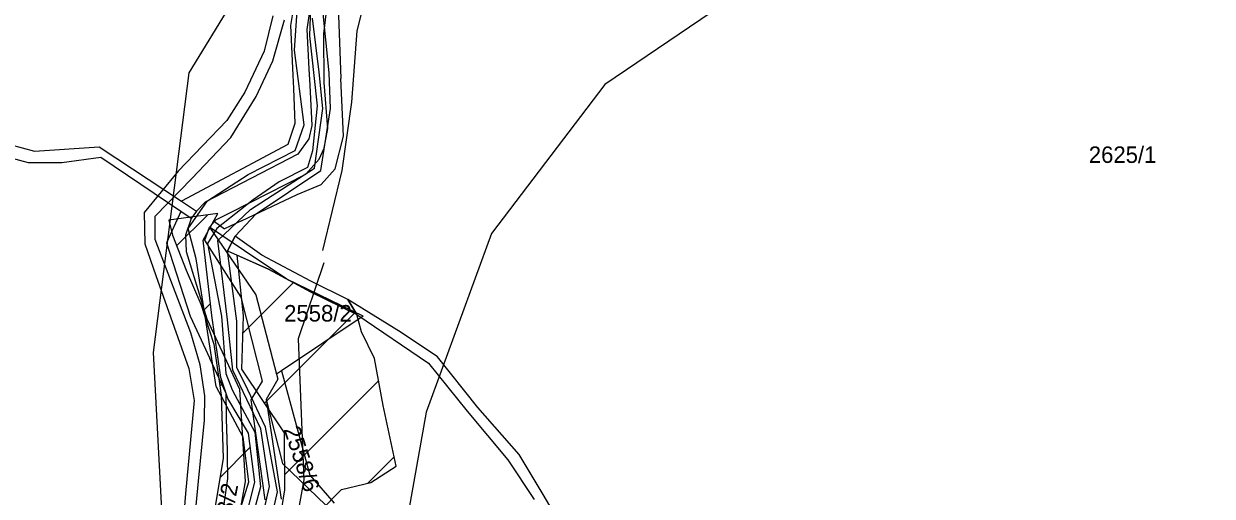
# Model space of a CAD drawing. Extents: x -564810 to -550519, y -1045831 to -1034011.
# Drawn here: x -551637.3 to -551270.6, y -1037442.3 to -1037296.5 of the extents above; entities that cross this region are included whole.
import ezdxf

# ---------------------------------------------------------------- set-up
doc = ezdxf.new("R2010")
doc.units = 0
for name, color, linetype in [('KN stav', 7, 'Continuous'), ('Lesní porost', 7, 'Continuous'), ('Parcelní čísla', 7, 'Continuous'), ('Polní cesty stavající', 7, 'Continuous'), ('STG', 7, 'Continuous'), ('vodní toky', 7, 'Continuous'), ('Vrstva 18', 7, 'Continuous'), ('Vrstva 33', 7, 'Continuous')]:
    doc.layers.add(name, color=color, linetype=linetype)

msp = doc.modelspace()

# ---------------------------------------------------------------- linework, layer by layer
at = {"layer": 'KN stav'}
for p, q in [((-551549.14, -1037261), (-551555, -1037297.05)), ((-551547.78, -1037282.89), (-551549.99, -1037298.21)), ((-551544.79, -1037299.56), (-551542.87, -1037283.57)), ((-551540.36, -1037291.18), (-551539.45, -1037313.36)), ((-551555, -1037297.05), (-551554.32, -1037312.32)), ((-551549.99, -1037298.21), (-551549.36, -1037310.41)), ((-551544.6, -1037314.59), (-551544.79, -1037299.56)), ((-551554.32, -1037312.32), (-551554.13, -1037316.42)), ((-551549.36, -1037310.41), (-551549.1, -1037315.39)), ((-551554.13, -1037316.42), (-551553.65, -1037327.22)), ((-551549.1, -1037315.39), (-551548.45, -1037327.89)), ((-551543.54, -1037328.85), (-551544.6, -1037314.59)), ((-551538.72, -1037331.17), (-551539.45, -1037313.36)), ((-551553.65, -1037327.22), (-551555.87, -1037333.7)), ((-551654.6, -1037330.27), (-551634.05, -1037335.84)), ((-551548.45, -1037327.89), (-551549.41, -1037331.94)), ((-551544.6, -1037334.83), (-551543.54, -1037328.85)), ((-551541.23, -1037341.28), (-551538.72, -1037331.17)), ((-551635.85, -1037339.35), (-551655.43, -1037334.29)), ((-551634.05, -1037335.84), (-551614.07, -1037334.46)), ((-551614.07, -1037334.46), (-551588.68, -1037351.23)), ((-551555.87, -1037333.7), (-551588.68, -1037351.23)), ((-551549.41, -1037331.94), (-551552.72, -1037336.73)), ((-551546.14, -1037338.3), (-551544.6, -1037334.83)), ((-551613.54, -1037337.73), (-551625.54, -1037339.35)), ((-551588.88, -1037354.41), (-551613.54, -1037337.73)), ((-551552.72, -1037336.73), (-551581.34, -1037351.54)), ((-551550.26, -1037342.85), (-551546.14, -1037338.3)), ((-551625.54, -1037339.35), (-551635.85, -1037339.35)), ((-551545.56, -1037346.1), (-551541.23, -1037341.28)), ((-551573.54, -1037354.7), (-551550.26, -1037342.85)), ((-551570.18, -1037357.29), (-551552.98, -1037349.14)), ((-551552.98, -1037349.14), (-551545.56, -1037346.1)), ((-551588.68, -1037351.23), (-551583.99, -1037354.33)), ((-551581.34, -1037351.54), (-551583.99, -1037354.33)), ((-551588.88, -1037354.41), (-551593.33, -1037364.13)), ((-551585.71, -1037356.56), (-551588.88, -1037354.41)), ((-551585.71, -1037356.56), (-551587.46, -1037361.73)), ((-551583.99, -1037354.33), (-551585.71, -1037356.56)), ((-551578.51, -1037357.51), (-551578.03, -1037356.98)), ((-551578.03, -1037356.98), (-551573.54, -1037354.7)), ((-551581.5, -1037363.31), (-551580.06, -1037359.22)), ((-551580.06, -1037359.22), (-551578.51, -1037357.51)), ((-551580.06, -1037359.22), (-551565.71, -1037380.15)), ((-551569.26, -1037366.52), (-551580.06, -1037359.22)), ((-551578.51, -1037357.51), (-551575.41, -1037359.77)), ((-551570.18, -1037357.29), (-551575.41, -1037359.77)), ((-551593.33, -1037364.13), (-551586.01, -1037386.71)), ((-551587.46, -1037361.73), (-551587.26, -1037366.8)), ((-551570.22, -1037380.83), (-551581.5, -1037363.31)), ((-551587.26, -1037366.8), (-551580.8, -1037387.55)), ((-551556.19, -1037375.35), (-551569.26, -1037366.52)), ((-551532.57, -1037386.75), (-551556.19, -1037375.35)), ((-551563.67, -1037406.75), (-551570.22, -1037380.83)), ((-551565.71, -1037380.15), (-551559.34, -1037404.6)), ((-551586.01, -1037386.71), (-551579.91, -1037399.79)), ((-551580.8, -1037387.55), (-551570.74, -1037409.2)), ((-551532.57, -1037386.75), (-551557.8, -1037403.58)), ((-551574.89, -1037410.55), (-551579.91, -1037399.79)), ((-551557.8, -1037403.58), (-551559.34, -1037404.6)), ((-551559.34, -1037404.6), (-551558.94, -1037406.12)), ((-551557.8, -1037403.58), (-551549.04, -1037435.77)), ((-551567.21, -1037412.59), (-551563.67, -1037406.75)), ((-551558.94, -1037406.12), (-551562.54, -1037412.48)), ((-551574.71, -1037423.11), (-551574.89, -1037410.55)), ((-551570.74, -1037409.2), (-551569.04, -1037437.75)), ((-551562.83, -1037443.42), (-551567.21, -1037412.59)), ((-551562.54, -1037412.48), (-551557.93, -1037443.23)), ((-551562.54, -1037412.48), (-551557.46, -1037432.16)), ((-551574.71, -1037423.11), (-551574.51, -1037436.84)), ((-551557.46, -1037432.16), (-551538.81, -1037450.22)), ((-551574.51, -1037436.84), (-551581.67, -1037488.42)), ((-551549.04, -1037435.77), (-551541.51, -1037444.4)), ((-551569.04, -1037437.75), (-551573.47, -1037462.66))]:
    msp.add_line(p, q, dxfattribs=at)
at = {"layer": 'Lesní porost'}
for p, q in [((-551577.41, -1037355.08), (-551592.53, -1037357.12)), ((-551590.15, -1037365.03), (-551580.64, -1037355.52)), ((-551581.97, -1037363.24), (-551577.41, -1037355.08)), ((-551592.53, -1037357.12), (-551591.42, -1037361.75)), ((-551591.42, -1037361.75), (-551587.24, -1037372.53)), ((-551579.28, -1037386.47), (-551581.97, -1037363.24)), ((-551561.81, -1037372.19), (-551571.55, -1037367.87)), ((-551571.55, -1037367.87), (-551569.66, -1037386.57)), ((-551587.24, -1037372.53), (-551582.74, -1037382.99)), ((-551548.81, -1037379.24), (-551561.81, -1037372.19)), ((-551569.81, -1037392.05), (-551554.12, -1037376.36)), ((-551534.51, -1037386.16), (-551548.81, -1037379.24)), ((-551582.74, -1037382.99), (-551578.71, -1037395.36)), ((-551582.03, -1037385.18), (-551579.7, -1037382.86)), ((-551563.08, -1037413.61), (-551535.27, -1037385.79)), ((-551533.08, -1037391.53), (-551534.51, -1037386.16)), ((-551576.53, -1037405.69), (-551579.28, -1037386.47)), ((-551529.12, -1037399.79), (-551533.08, -1037391.53)), ((-551578.71, -1037395.36), (-551576.43, -1037411.12)), ((-551526.46, -1037414.29), (-551529.12, -1037399.79)), ((-551576.84, -1037408.28), (-551575.96, -1037407.4)), ((-551574.4, -1037412.1), (-551576.53, -1037405.69)), ((-551556.89, -1037435.69), (-551527.86, -1037406.67)), ((-551576.43, -1037411.12), (-551575.77, -1037430.58)), ((-551568, -1037422.82), (-551574.4, -1037412.1)), ((-551522.46, -1037433), (-551526.46, -1037414.29)), ((-551566.04, -1037437.9), (-551568, -1037422.82)), ((-551557.01, -1037422.74), (-551556.84, -1037440.36)), ((-551576.77, -1037436.49), (-551567.44, -1037427.16)), ((-551531.13, -1037438.23), (-551523.07, -1037430.16)), ((-551575.77, -1037430.58), (-551578.38, -1037446.09)), ((-551530.28, -1037438.02), (-551522.46, -1037433)), ((-551570.84, -1037456.9), (-551566.04, -1037437.9)), ((-551556.84, -1037440.36), (-551559, -1037452.99)), ((-551546.07, -1037447.06), (-551539.25, -1037440.2)), ((-551539.25, -1037440.2), (-551530.28, -1037438.02))]:
    msp.add_line(p, q, dxfattribs=at)
msp.add_lwpolyline([(-551569.66, -1037386.57), (-551570.11, -1037403.05), (-551557.01, -1037422.74)], dxfattribs=at)
at = {"layer": 'Polní cesty stavající'}
for p, q in [((-551560.51, -1037293.99), (-551563.12, -1037304.98)), ((-551560.5, -1037307.88), (-551556.86, -1037295.26)), ((-551563.12, -1037304.98), (-551569.1, -1037317.59)), ((-551565.59, -1037318.95), (-551560.5, -1037307.88)), ((-551569.1, -1037317.59), (-551574.68, -1037326.35)), ((-551573.46, -1037331.57), (-551565.59, -1037318.95)), ((-551574.68, -1037326.35), (-551589.67, -1037341.96)), ((-551585.5, -1037344.23), (-551573.46, -1037331.57)), ((-551589.67, -1037341.96), (-551600.21, -1037354.68)), ((-551596.83, -1037355.81), (-551585.5, -1037344.23)), ((-551600.21, -1037354.68), (-551600.01, -1037364.38)), ((-551596.74, -1037363.01), (-551596.83, -1037355.81)), ((-551600.01, -1037364.38), (-551596.55, -1037374.13)), ((-551585.8, -1037391.91), (-551596.74, -1037363.01)), ((-551572.05, -1037362.01), (-551574.5, -1037366.56)), ((-551563.89, -1037367.88), (-551572.05, -1037362.01)), ((-551574.5, -1037366.56), (-551561.82, -1037372.18)), ((-551548.75, -1037375.94), (-551563.89, -1037367.88)), ((-551596.55, -1037374.13), (-551586.41, -1037402.87)), ((-551561.82, -1037372.18), (-551548.82, -1037379.23)), ((-551537.37, -1037381.59), (-551548.75, -1037375.94)), ((-551548.82, -1037379.23), (-551534.52, -1037386.16)), ((-551520.84, -1037391.75), (-551537.37, -1037381.59)), ((-551537.37, -1037381.59), (-551534.52, -1037386.16)), ((-551534.52, -1037386.16), (-551537.37, -1037381.59)), ((-551534.52, -1037386.16), (-551512.41, -1037401.18)), ((-551582.88, -1037401.79), (-551585.8, -1037391.91)), ((-551509.69, -1037399.3), (-551520.84, -1037391.75)), ((-551497.25, -1037414.92), (-551509.69, -1037399.3)), ((-551586.41, -1037402.87), (-551584.78, -1037412.74)), ((-551581.42, -1037411.32), (-551582.88, -1037401.79)), ((-551512.41, -1037401.18), (-551500.5, -1037416)), ((-551581.53, -1037418.85), (-551581.42, -1037411.32)), ((-551584.78, -1037412.74), (-551587.46, -1037441.42)), ((-551484.45, -1037429.46), (-551497.25, -1037414.92)), ((-551583.45, -1037437.67), (-551581.53, -1037418.85)), ((-551500.5, -1037416), (-551487.94, -1037431.02)), ((-551477.07, -1037441.77), (-551484.45, -1037429.46)), ((-551487.94, -1037431.02), (-551479.85, -1037443.35)), ((-551584.87, -1037453.46), (-551583.45, -1037437.67)), ((-551587.46, -1037441.42), (-551588.3, -1037452.11)), ((-551466.24, -1037460.09), (-551477.07, -1037441.77))]:
    msp.add_line(p, q, dxfattribs=at)
at = {"layer": 'STG'}
for points in [[(-552085.98, -1037726.88), (-551997.79, -1037717.69), (-551885.73, -1037708.5), (-551777.34, -1037693.8), (-551650.58, -1037618.46), (-551597.31, -1037544.96), (-551593.63, -1037467.78), (-551597.31, -1037397.95), (-551586.28, -1037311.58), (-551545.87, -1037245.43), (-551516.47, -1037186.63), (-551459.52, -1037149.88), (-551378.69, -1037116.8), (-551273.98, -1037100.26), (-551202.33, -1037076.37), (-551108.64, -1037028.6), (-550987.39, -1036980.82), (-550890.39, -1036925.69), (-550831.6, -1036883.43), (-550758.12, -1036817.27), (-550710.36, -1036749.28), (-550693.82, -1036703.34), (-550693.82, -1036639.03), (-550758.12, -1036504.88)], [(-550827.93, -1037355.69), (-550859.16, -1037254.62), (-550894.07, -1037238.08), (-550932.64, -1037234.41), (-550974.9, -1037230.73), (-551004.29, -1037236.24), (-551042.87, -1037236.24), (-551074.1, -1037228.89), (-551120.03, -1037230.73), (-551145.75, -1037227.06), (-551221.07, -1037239.92), (-551287.2, -1037252.78), (-551358.85, -1037265.64), (-551412.13, -1037284.02), (-551458.06, -1037315.26), (-551492.96, -1037361.2), (-551513.17, -1037416.33), (-551527.86, -1037499.02)]]:
    msp.add_lwpolyline(points, dxfattribs=at)
at = {"layer": 'vodní toky'}
for p, q in [((-551548.65, -1037285.74), (-551549.21, -1037300.16)), ((-551543.06, -1037311.66), (-551545.12, -1037291.25)), ((-551549.21, -1037300.16), (-551547.8, -1037312.49)), ((-551547.8, -1037312.49), (-551546.77, -1037321.78)), ((-551542.68, -1037322.59), (-551543.06, -1037311.66)), ((-551546.77, -1037321.78), (-551548.19, -1037335.66)), ((-551545.66, -1037341.77), (-551542.68, -1037322.59)), ((-551565.58, -1037355.16), (-551545.66, -1037341.77)), ((-551558.52, -1037345.21), (-551566.5, -1037350.86)), ((-551566.5, -1037350.86), (-551577.78, -1037359.66)), ((-551572.05, -1037362.01), (-551565.58, -1037355.16)), ((-551577.78, -1037359.66), (-551580.68, -1037364.33)), ((-551580.68, -1037364.33), (-551576.29, -1037386.75)), ((-551574.5, -1037366.56), (-551572.05, -1037362.01)), ((-551571.58, -1037388.31), (-551574.5, -1037366.56)), ((-551576.29, -1037386.75), (-551574.94, -1037404.46)), ((-551571.63, -1037402.61), (-551571.58, -1037388.31)), ((-551574.94, -1037404.46), (-551572.99, -1037409.42)), ((-551568.15, -1037409.44), (-551571.63, -1037402.61)), ((-551572.99, -1037409.42), (-551565.99, -1037422.55)), ((-551562.77, -1037421.02), (-551568.15, -1037409.44)), ((-551565.99, -1037422.55), (-551564.33, -1037439.35)), ((-551559.02, -1037440.96), (-551562.77, -1037421.02)), ((-551564.33, -1037439.35), (-551568.83, -1037456.3)), ((-551562.61, -1037456.47), (-551559.02, -1037440.96))]:
    msp.add_line(p, q, dxfattribs=at)
msp.add_lwpolyline([(-551548.19, -1037335.66), (-551549.76, -1037340.8), (-551558.52, -1037345.21)], dxfattribs=at)
at = {"layer": 'Vrstva 18'}
for points in [[(-551219.35, -1037171.83), (-551273.07, -1037176.1), (-551316.99, -1037173.96), (-551342.14, -1037182.07), (-551357.92, -1037197.84), (-551387.33, -1037223), (-551432.53, -1037233.23), (-551453.63, -1037234.19), (-551488.38, -1037251.46), (-551528.78, -1037275.97), (-551534.54, -1037298.67), (-551536.24, -1037320.63), (-551539.23, -1037341.74), (-551545.19, -1037366.47)], [(-551571.94, -1037450.67), (-551567.89, -1037437.88), (-551569.59, -1037424.02), (-551577.91, -1037408.46), (-551584.09, -1037369.02), (-551586.65, -1037359.64), (-551580.68, -1037351.12), (-551568.1, -1037343.02), (-551553.6, -1037335.55), (-551550.83, -1037327.67), (-551553.82, -1037304.64), (-551552.11, -1037280.34)], [(-551544.76, -1037370.3), (-551552.65, -1037393.75), (-551550.94, -1037437.24), (-551554.78, -1037458.77), (-551534.74, -1037459.2), (-551525.57, -1037497.78), (-551513.85, -1037519.32), (-551505.75, -1037542.98), (-551507.66, -1037555.13), (-551531.75, -1037621), (-551553.07, -1037607.79), (-551573.11, -1037603.52), (-551613.4, -1037630.17), (-551651.35, -1037683.89), (-551693.56, -1037722.69)]]:
    msp.add_lwpolyline(points, dxfattribs=at)
at = {"layer": 'Vrstva 33'}
msp.add_lwpolyline([(-551566.42, -1037460.75), (-551561.55, -1037439.24), (-551564.16, -1037421.51), (-551572.79, -1037403.43), (-551574.45, -1037387.8), (-551577.49, -1037363.37), (-551567.35, -1037353.8), (-551547.64, -1037341.05), (-551545.04, -1037322.6), (-551546.2, -1037311.43), (-551548.23, -1037294.76)], dxfattribs=at)

# ---------------------------------------------------------------- texts
at = {"layer": 'Parcelní čísla'}
for s, p in [('2625/1', (-551308.71, -1037339.43)), ('2558/2', (-551556.99, -1037388.38))]:
    msp.add_text(s, height=5.1, dxfattribs=at).set_placement(p)
for s, rotation, p in [('2558/6', 288.1981, (-551557.18, -1037421.61)), ('2543/2', 78.9844, (-551575.1, -1037459.32))]:
    msp.add_text(s, height=5.1, rotation=rotation, dxfattribs=at).set_placement(p)

doc.saveas('drawing.dxf')
